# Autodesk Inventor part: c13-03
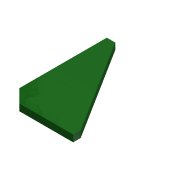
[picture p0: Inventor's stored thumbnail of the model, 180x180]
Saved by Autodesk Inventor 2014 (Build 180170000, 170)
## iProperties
Created: 2011-01
Part Number: c13-03
Material: Generic
Document SubType Name: Modeling
Designer: Thom Tremblay
Density: 1 g/cm^3
Appearance: Forest Green
Author: Thom Tremblay
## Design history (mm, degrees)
sketch "Sketch1"
  geometry: L1 (0, 0)-(0, 120); L2 (10, 120)-(80, 8.885); L3 (80, 0)-(0, 0); L4 (16, 0)-(0, 16); L5 (10, 120)-(0, 120); L6 (80, 8.885)-(80, 0)
  constraints: 12 end point, 3 perpendicular, 2 point on line, 1 vertical
  dimensions: "d2" = 16 distance of L4.start L1.start; "d3" = 45 deg angle of L3 L4; "d6" = 120 distance between parallel lines of L5 L3; "d7" = 10 distance of L2.start L1.end; "d8" = 80 distance of L3.start L1.start
extrude "Extrusion1" new body sketch "Sketch1" stored distance "d4" = 8; taper "d5" = 0 deg
body "Solid1"
